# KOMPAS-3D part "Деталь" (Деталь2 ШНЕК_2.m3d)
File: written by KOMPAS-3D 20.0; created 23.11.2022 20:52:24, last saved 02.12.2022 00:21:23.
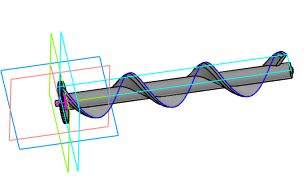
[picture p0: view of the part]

Document properties: Полное имя файла: C:\Users\Семья\Desktop\ДЕТАЛИ ДЛЯ СБОРЩИКА БОРЩЕВИКА\Деталь2 ШНЕК_2.m3d

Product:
- Part/product: Деталь
    Масса: 0.0612446
  - Body: Тело 2
      Масса: 0.00490374
  - Body: Тело 1
      Масса: 0.0563409

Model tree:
1. Эскиз:1
2. Элемент выдавливания:1
     Расстояние 1 = 1
3. Эскиз:3  (with: Элемент выдавливания:1)
4. Элемент выдавливания:4
     Расстояние 1 = 2
5. Эскиз:5  (with: Элемент выдавливания:4)
6. Элемент выдавливания:5
     Расстояние 1 = 114
7. Эскиз:6  (with: Элемент выдавливания:5)
8. Элемент выдавливания:6
     Расстояние 1 = 1
9. Эскиз:7  (with: Элемент выдавливания:4)
10. Спираль:1
     Число витков = 3; Шаг = 38; Высота = 114; Диаметр 1 = 20; Диаметр 2 = 10
11. Плоскость через ребро и точку:1
12. Эскиз:12
13. Элемент по траектории:2
14. Эскиз:13  (with: Элемент по траектории:2, Элемент выдавливания:4)
15. Элемент выдавливания:8
     Расстояние 2 = 10
16. Элемент выдавливания:9  (with: Элемент выдавливания:1)
     Расстояние 1 = 2
17. Смещенная плоскость:1  (with: ЛСК (Шестерня цилиндрическая с внешними зубьями):1, Шестерня цилиндрическая с внешними зубьями:1, Плоскость XY, Плоскость ZX, Плоскость ZY, Ось X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)  (labels: &Фаска (Шестерня цилиндрическая с внешними зубьями):1)
     Расстояние = 5; Ось X. Y = -1; Ось Y. X = 1; Ось Z. Z = 1; Точка начала. Y = 5; Угол 1 = 360
18. Эскиз для винтовой линии (Шестерня цилиндрическая с внешними зубьями):1  (with: Винтовая линия (Шестерня цилиндрическая с внешними зубьями):1, Шестерня цилиндрическая с внешними зубьями:1, Впадина (Шестерня цилиндрическая с внешними зубьями):1, Впадина прямая (Шестерня цилиндрическая с внешними зубьями):1, Массив косых впадин (Шестерня цилиндрическая с внешними зубьями):1)  (2 pattern instances)
     Число витков = 0.00277425; Шаг = -141330; Направление навивки = -3.2425e-05; Смещение 2 = 10
19. Впадина прямая (Шестерня цилиндрическая с внешними зубьями):1  (with: Смещенная плоскость:1, Массив прямых впадин (Шестерня цилиндрическая с внешними зубьями):1, Шестерня цилиндрическая с внешними зубьями:1)  (40 pattern instances)
     N 1 = 1; Шаг 1 = 1; Номер 1 = 1
20. Впадина косая (Шестерня цилиндрическая с внешними зубьями):1  (with: Смещенная плоскость:1, Винтовая линия (Шестерня цилиндрическая с внешними зубьями):1, Впадина прямая (Шестерня цилиндрическая с внешними зубьями):1)  (38 pattern instances)
     N 1 = 1; Шаг 1 = 1; Номер 1 = 1
21. Шестерня цилиндрическая с внешними зубьями:1
22. Элемент выдавливания:24  (with: Элемент выдавливания:4)
     Расстояние 2 = 1
23. Элемент выдавливания:25  (with: Элемент выдавливания:24)
     Расстояние 2 = 1
24. Масштабирование:2
     Коэффициент = 5
25. Масштабирование:5
     Коэффициент = 1
26. Масштабирование:6
     Коэффициент = 0.2
27. Масштабирование:7
     Коэффициент = 0.2

Expressions: (VGExtS_1_z*VGExtS_1_M)/COSD(VGExtS_1_Beta); 360/VGExtS_1_z
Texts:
  SHAFT3D
  Количество отображаемых зубьев
  Угол наклона линии зубьев
  Шаг по кольцевому направлению
  (VGExtS_1_Beta>0)?(M_PI*VGExtS_1_z*VGExtS_1_M/SIND(VGExtS_1_Beta)):1000
  (VGExtS_1_Da<=0||VGExtS_1_Da>5e+7)?25:VGExtS_1_Da
  (VGExtS_1_H<=0||VGExtS_1_H>5e+7)?25:VGExtS_1_H
  VGExtS_1_zz<VGExtS_1_z?(VGExtS_1_zz+1):VGExtS_1_z
  (VGExtS_1_zz<=0||VGExtS_1==1)||(VGExtS_1_Beta>0)?1:0
  (VGExtS_1_zz<=0||VGExtS_1==1)||(VGExtS_1_Beta<=0)?1:0
  (VGExtS_1==1)||(VGExtS_1_Beta<=0)?1:0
